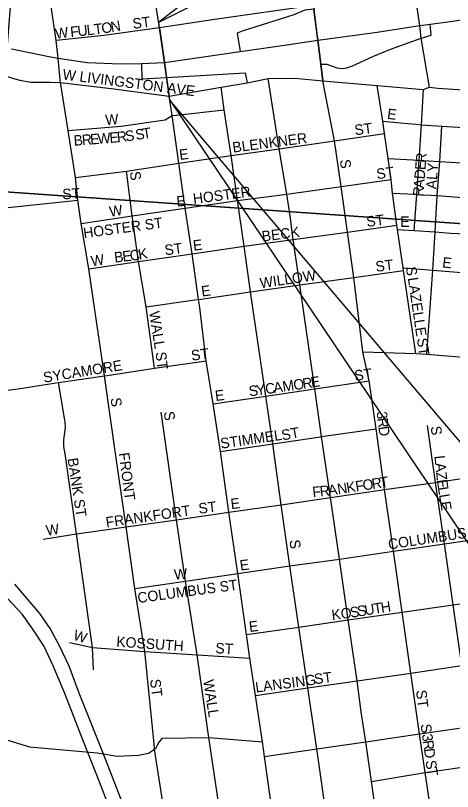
# Model space of a CAD drawing. Extents: x 0 to 34, y -6.2 to 22.
# Drawn here: x 6.622 to 7.019, y 16.756 to 17.461 of the extents above; entities that cross this region are included whole.
import ezdxf

# ---------------------------------------------------------------- set-up
doc = ezdxf.new("R2010")
doc.units = 0
for name, color, linetype in [('GM_X_City_Street', 7, 'Continuous'), ('GM_X_City_Street_Text', 7, 'Continuous'), ('GM_X_Interchange_Ramps', 7, 'Continuous'), ('GM_X_Interstate_Route', 7, 'Continuous'), ('GM_X_Rail_Line', 7, 'Continuous'), ('GM_X_Section', 7, 'Continuous'), ('GM_X_US_Route', 7, 'Continuous'), ('SH_Data', 7, 'Continuous')]:
    doc.layers.add(name, color=color, linetype=linetype)

msp = doc.modelspace()

# ---------------------------------------------------------------- linework, layer by layer
at = {"layer": 'GM_X_City_Street'}
for points in [[(6.66228, 17.40254), (6.66049, 17.4222), (6.65856, 17.43834), (6.64528, 17.52991), (6.63896, 17.57505), (6.63208, 17.62111), (6.62558, 17.66735), (6.61917, 17.71353), (6.60471, 17.80555), (6.59247, 17.89732), (6.57924, 17.99099), (6.57205, 18.04143), (6.57176, 18.04339)], [(6.75255, 17.44995), (6.74524, 17.49671), (6.73878, 17.54435), (6.72556, 17.63506), (6.7249, 17.63939)], [(6.98877, 16.80787), (6.9808, 16.86316), (6.97295, 16.91857), (6.965, 16.97414), (6.95682, 17.03003), (6.94936, 17.08532), (6.94288, 17.12895), (6.93734, 17.15524), (6.92909, 17.22293), (6.92322, 17.2641), (6.91739, 17.30569), (6.91152, 17.34717), (6.90101, 17.40179), (6.89903, 17.41691), (6.89623, 17.43861), (6.89274, 17.46692), (6.89426, 17.47051)], [(6.75255, 17.44995), (6.70191, 17.44305), (6.65856, 17.43834)], [(6.74789, 16.79577), (6.73913, 16.883), (6.73008, 16.94009), (6.72224, 16.99619), (6.71312, 17.05874), (6.70239, 17.13346), (6.68837, 17.23069), (6.68116, 17.27185), (6.6784, 17.29311), (6.67621, 17.31372), (6.66958, 17.35651), (6.66251, 17.40009), (6.66228, 17.40254)], [(6.66251, 17.40009), (6.71103, 17.39445), (6.76126, 17.38765)], [(6.98129, 16.36058), (6.98519, 16.42372), (6.98694, 16.45905), (6.98628, 16.46842), (6.9808, 16.50717), (6.97514, 16.54732), (6.97044, 16.58742), (6.95853, 16.6688), (6.94981, 16.73103), (6.94497, 16.76478), (6.93985, 16.80077), (6.93574, 16.82808), (6.93201, 16.85622), (6.92402, 16.91156), (6.91591, 16.96683), (6.90769, 17.02289), (6.89981, 17.07827), (6.89356, 17.12168), (6.88008, 17.21618), (6.87406, 17.2574), (6.87129, 17.27883), (6.86814, 17.29881), (6.86105, 17.33997), (6.85135, 17.40376)], [(6.98549, 17.15372), (6.97417, 17.22937), (6.97381, 17.23183), (6.96864, 17.26653), (6.96811, 17.27053), (6.96426, 17.29965), (6.96285, 17.31213), (6.96023, 17.33122), (6.9569, 17.3538), (6.9554, 17.36491), (6.95016, 17.39751)], [(6.81124, 17.37548), (6.80857, 17.39581)], [(6.98398, 17.26554), (6.98618, 17.29844), (6.9883, 17.32944), (6.99046, 17.36181), (6.99247, 17.39393)], [(6.66958, 17.35651), (6.71753, 17.36052), (6.75764, 17.36611), (6.76389, 17.37022)], [(6.76389, 17.37022), (6.768, 17.37039), (6.81124, 17.37548)], [(6.9475, 16.29952), (6.94602, 16.36266), (6.94447, 16.42634), (6.94281, 16.46308), (6.93994, 16.48326), (6.9361, 16.51036), (6.9247, 16.59085), (6.91432, 16.66217), (6.89538, 16.79423), (6.88727, 16.84982), (6.87921, 16.90505), (6.87103, 16.96084), (6.86295, 17.01634), (6.85545, 17.07171), (6.84898, 17.11505), (6.8353, 17.20994), (6.82944, 17.25134), (6.82321, 17.29303), (6.81749, 17.33372), (6.81124, 17.37548)], [(6.9554, 17.36491), (6.97135, 17.36342), (6.98538, 17.36224)], [(6.98538, 17.36224), (6.99046, 17.36181), (7.00898, 17.36059), (7.02377, 17.35959), (7.04305, 17.35808), (7.06105, 17.35702), (7.0768, 17.35586), (7.0955, 17.35463)], [(7.00493, 17.30135), (7.00703, 17.32844), (7.00898, 17.36059)], [(6.76997, 17.32682), (6.81749, 17.33372), (6.86105, 17.33997), (6.91152, 17.34717), (6.9569, 17.3538)], [(6.67621, 17.31372), (6.72252, 17.31971), (6.76997, 17.32682)], [(6.96023, 17.33122), (6.9883, 17.32944), (7.00138, 17.32874), (7.00703, 17.32844), (7.02205, 17.32761), (7.04124, 17.32633), (7.05928, 17.32541), (7.07513, 17.32357), (7.09333, 17.32258), (7.17932, 17.31649), (7.21272, 17.31416), (7.2772, 17.31028), (7.32879, 17.30679), (7.37022, 17.30248), (7.37497, 17.30216)], [(6.74807, 17.14058), (6.74031, 17.19619), (6.73351, 17.23735), (6.72774, 17.27907), (6.72252, 17.31971)], [(6.76513, 17.28436), (6.77573, 17.28588), (6.82321, 17.29303), (6.86814, 17.29881), (6.91739, 17.30569), (6.96285, 17.31213)], [(6.96426, 17.29965), (6.98443, 17.29854)], [(6.99551, 17.15319), (7.00082, 17.22971), (7.00284, 17.26431), (7.00463, 17.29736), (7.00493, 17.30135)], [(6.50046, 17.26128), (6.55735, 17.27777), (6.56934, 17.28141), (6.58298, 17.2832), (6.6784, 17.29311)], [(6.98443, 17.29854), (6.98618, 17.29844), (7.00463, 17.29736), (7.02008, 17.29616), (7.03888, 17.29482), (7.05744, 17.29349), (7.07258, 17.29242), (7.09118, 17.29121), (7.09526, 17.29083)], [(6.68116, 17.27185), (6.72774, 17.27907), (6.76513, 17.28436)], [(6.78201, 17.24433), (6.82944, 17.25134), (6.87406, 17.2574), (6.92322, 17.2641), (6.96811, 17.27053)], [(6.96864, 17.26653), (6.98398, 17.26554), (7.00284, 17.26431), (7.01697, 17.26336), (7.03651, 17.26217), (7.05493, 17.26085), (7.07038, 17.25988), (7.08894, 17.25868), (7.108, 17.25664), (7.14201, 17.25363), (7.17553, 17.25134), (7.17773, 17.25111), (7.21989, 17.24793), (7.25478, 17.24516), (7.27152, 17.2441), (7.29026, 17.24266), (7.32481, 17.24037), (7.36585, 17.23773), (7.40163, 17.23554), (7.44233, 17.23315), (7.44451, 17.233)], [(6.68837, 17.23069), (6.73351, 17.23735), (6.78201, 17.24433)], [(6.78795, 17.20304), (6.8353, 17.20994), (6.88008, 17.21618), (6.92909, 17.22293), (6.97417, 17.22937)], [(6.97381, 17.23183), (7.00082, 17.22971), (7.03432, 17.22694), (7.06727, 17.22478)], [(6.74031, 17.19619), (6.7868, 17.20303)], [(6.93734, 17.15524), (6.98549, 17.15372), (6.99551, 17.15319), (7.02829, 17.15034)], [(6.70489, 17.13385), (6.74807, 17.14058), (6.79494, 17.14722)], [(6.64486, 17.12489), (6.66076, 17.12736), (6.70239, 17.13346), (6.70489, 17.13385)], [(6.54599, 17.12007), (6.55145, 17.11592), (6.55621, 17.11505), (6.56156, 17.11407), (6.57194, 17.11497), (6.62409, 17.12166), (6.64486, 17.12489)], [(6.69265, 16.86615), (6.69163, 16.88666), (6.67705, 16.98975), (6.66663, 17.06255), (6.66555, 17.06931), (6.66556, 17.07234), (6.66557, 17.07537), (6.66707, 17.08641), (6.66678, 17.09137), (6.66619, 17.0949), (6.66076, 17.12736)], [(6.80136, 17.10816), (6.84898, 17.11505), (6.89356, 17.12168), (6.94288, 17.12895)], [(6.8291, 16.58565), (6.82024, 16.64708), (6.81213, 16.70338), (6.80479, 16.75388), (6.79742, 16.80456), (6.78661, 16.87995), (6.77622, 16.94687), (6.76796, 17.00266), (6.75398, 17.1005)], [(7.00322, 17.03664), (6.99583, 17.08829)], [(6.89878, 17.07812), (6.89981, 17.07827), (6.94936, 17.08532)], [(6.80781, 17.06482), (6.85545, 17.07171), (6.89878, 17.07812)], [(6.81561, 17.00952), (6.86295, 17.01634), (6.90769, 17.02289), (6.95682, 17.03003), (7.00322, 17.03664), (7.04287, 17.04245)], [(7.04542, 16.74501), (7.04031, 16.77954), (7.03508, 16.81471), (7.02724, 16.87005), (7.01928, 16.92531), (7.01137, 16.98061), (7.00322, 17.03664)], [(6.69646, 16.99251), (6.72224, 16.99619), (6.76796, 17.00266), (6.81561, 17.00952)], [(6.82353, 16.95368), (6.87103, 16.96084), (6.91591, 16.96683), (6.965, 16.97414), (7.01137, 16.98061), (7.05704, 16.98728), (7.10127, 16.99344), (7.13, 16.99743), (7.15851, 17.00116), (7.19129, 16.99884), (7.23458, 16.99599), (7.28124, 16.99293), (7.31163, 16.99092), (7.34133, 16.98882), (7.37633, 16.98634), (7.44129, 16.98221)], [(6.64686, 16.98514), (6.67705, 16.98975), (6.69646, 16.99251)], [(6.73008, 16.94009), (6.77622, 16.94687), (6.82353, 16.95368)], [(6.83156, 16.8982), (6.87921, 16.90505), (6.92402, 16.91156), (6.97295, 16.91857), (7.01928, 16.92531), (7.0653, 16.93194), (7.11013, 16.93831), (7.13803, 16.94224), (7.16549, 16.94618), (7.1679, 16.93411), (7.18697, 16.9335), (7.23038, 16.93054), (7.27701, 16.92747), (7.3069, 16.92549), (7.3368, 16.92357), (7.37158, 16.92099), (7.43727, 16.91687)], [(6.67066, 16.89115), (6.69163, 16.88666), (6.73913, 16.883), (6.78661, 16.87995), (6.83466, 16.87683)], [(6.83974, 16.84289), (6.88727, 16.84982), (6.93201, 16.85622), (6.9808, 16.86316), (7.02724, 16.87005), (7.07341, 16.87657), (7.11767, 16.88261), (7.14621, 16.88683), (7.17434, 16.89007), (7.22701, 16.88596)], [(6.99321, 16.80853), (7.03508, 16.81471), (7.08129, 16.82115), (7.1258, 16.82753), (7.15409, 16.83157), (7.18254, 16.83535), (7.18811, 16.83513), (7.22314, 16.83236), (7.24974, 16.83039), (7.26894, 16.82897), (7.29909, 16.82673), (7.36453, 16.82192), (7.43076, 16.81698), (7.51924, 16.81054), (7.59763, 16.80457), (7.62864, 16.80232), (7.66394, 16.79971), (7.72826, 16.79494), (7.79318, 16.79013), (7.85815, 16.78539)], [(6.52342, 16.82079), (6.5408, 16.82013), (6.54344, 16.81979), (6.58215, 16.81465), (6.60451, 16.80544), (6.63446, 16.7962), (6.69592, 16.79064), (6.71414, 16.78776), (6.73347, 16.78872), (6.74258, 16.79054), (6.74807, 16.79402), (6.74906, 16.79465), (6.75091, 16.79827), (6.75097, 16.79838)], [(6.84792, 16.78744), (6.89538, 16.79423), (6.93985, 16.80077), (6.98877, 16.80787), (6.99321, 16.80853)], [(6.99898, 16.7383), (6.99396, 16.7728), (6.98877, 16.80787)], [(6.75097, 16.79838), (6.75138, 16.79918), (6.75521, 16.80408), (6.79742, 16.80456), (6.84598, 16.80069)], [(6.94497, 16.76478), (6.99396, 16.7728), (7.04031, 16.77954), (7.08659, 16.78643), (7.13133, 16.79281), (7.18775, 16.80024), (7.21441, 16.80115)], [(6.82197, 16.4795), (6.80524, 16.56564), (6.80205, 16.57482), (6.77525, 16.6388), (6.76406, 16.69089), (6.74807, 16.79402), (6.74789, 16.79577)]]:
    msp.add_lwpolyline(points, dxfattribs=at)
at = {"layer": 'GM_X_Interchange_Ramps'}
for points in [[(6.89274, 17.46692), (6.88458, 17.46587), (6.87444, 17.46157), (6.82765, 17.44675), (6.82306, 17.44518), (6.82571, 17.42842)], [(6.89903, 17.41691), (6.90442, 17.41701), (6.91346, 17.41364), (6.91854, 17.41306), (6.92263, 17.41364), (6.92771, 17.4152), (6.94617, 17.42396), (6.96332, 17.43083), (6.99027, 17.44042), (6.99934, 17.44327), (6.99833, 17.45325)], [(6.56706, 17.44086), (6.56677, 17.42931), (6.58863, 17.41913), (6.60038, 17.41215), (6.60649, 17.40815), (6.61815, 17.40433), (6.62513, 17.40239), (6.63577, 17.40064), (6.65275, 17.40038), (6.66251, 17.40009)], [(6.73627, 17.41757), (6.73636, 17.40351), (6.75879, 17.40474), (6.83045, 17.40888), (6.83212, 17.39998)]]:
    msp.add_lwpolyline(points, dxfattribs=at)
at = {"layer": 'GM_X_Interstate_Route'}
for points in [[(6.99833, 17.45325), (7.01691, 17.45571), (7.03717, 17.45857)], [(6.89623, 17.43861), (6.95032, 17.44601), (6.98896, 17.45193), (6.99833, 17.45325)], [(6.73627, 17.41757), (6.75715, 17.41823), (6.82571, 17.42842), (6.86803, 17.43452)], [(6.86803, 17.43452), (6.87815, 17.43598), (6.89623, 17.43861)], [(6.61806, 17.4309), (6.61843, 17.43083), (6.652, 17.42394)], [(6.652, 17.42394), (6.66049, 17.4222)], [(6.66049, 17.4222), (6.68662, 17.41823), (6.71704, 17.41708), (6.73627, 17.41757)]]:
    msp.add_lwpolyline(points, dxfattribs=at)
at = {"layer": 'GM_X_Rail_Line'}
for points in [[(6.78009, 16.34957), (6.78107, 16.44035), (6.78316, 16.54147), (6.78232, 16.55809), (6.78023, 16.57625), (6.77813, 16.58701), (6.77464, 16.59958), (6.76836, 16.61801), (6.74663, 16.67459), (6.72551, 16.72798), (6.70331, 16.78509), (6.69397, 16.80865), (6.67947, 16.84509), (6.67031, 16.86947), (6.66188, 16.88751), (6.65327, 16.90374), (6.64366, 16.91742), (6.62118, 16.94416)], [(6.7671, 16.38071), (6.76836, 16.44803), (6.76892, 16.47122), (6.76961, 16.48602), (6.76975, 16.50684), (6.76989, 16.50963), (6.77017, 16.52695), (6.76919, 16.55237), (6.76766, 16.56592), (6.76473, 16.58226), (6.75869, 16.6048), (6.74536, 16.6426), (6.73956, 16.65773), (6.71953, 16.70877), (6.69497, 16.77185), (6.68219, 16.80403), (6.6666, 16.84455), (6.6559, 16.86984), (6.64738, 16.88797), (6.63745, 16.9033), (6.62776, 16.91688), (6.60983, 16.93579)]]:
    msp.add_lwpolyline(points, dxfattribs=at)
at = {"layer": 'GM_X_Section'}
msp.add_lwpolyline([(6.68124, 18.27598), (6.6863, 18.2758), (7.19351, 18.24276), (7.67976, 18.21035), (7.62278, 17.23025), (6.6036, 17.30139)], close=True, dxfattribs=at)
msp.add_lwpolyline([(6.6036, 17.30139), (7.62278, 17.23025), (7.55762, 16.2055), (6.69487, 16.2608), (6.69615, 16.47781), (6.69681, 16.58979), (6.67582, 16.60734), (6.66866, 16.61383), (6.66566, 16.61915), (6.66266, 16.62447), (6.66079, 16.62789), (6.65777, 16.63056), (6.65098, 16.63439), (6.63588, 16.64282), (6.61965, 16.65201)], dxfattribs=at)
at = {"layer": 'GM_X_US_Route'}
for points in [[(6.98896, 17.45193), (6.98469, 17.48087)], [(6.89426, 17.47051), (6.80056, 17.45702), (6.75255, 17.44995)], [(6.89426, 17.47051), (6.89274, 17.46692), (6.89583, 17.44191)], [(6.75255, 17.44995), (6.75707, 17.41882)], [(6.99784, 17.39587), (6.99027, 17.44042), (6.98896, 17.45193)], [(6.89583, 17.44191), (6.89623, 17.43861), (6.89903, 17.41691), (6.90101, 17.40179)], [(6.75707, 17.41882), (6.75715, 17.41823), (6.75879, 17.40474), (6.76126, 17.38765)], [(6.76126, 17.38765), (6.80857, 17.39581), (6.83212, 17.39998), (6.85135, 17.40376), (6.87552, 17.40425), (6.90101, 17.40179)], [(6.90101, 17.40179), (6.95016, 17.39751), (6.99247, 17.39393), (6.99784, 17.39587)], [(6.99784, 17.39587), (7.0054, 17.39504), (7.01921, 17.39406), (7.02348, 17.39373), (7.02628, 17.39356), (7.04551, 17.39274), (7.0636, 17.39132), (7.07925, 17.39031), (7.09763, 17.38929), (7.16685, 17.38468), (7.18356, 17.38368), (7.28127, 17.37762), (7.37333, 17.37121), (7.40788, 17.36948), (7.48776, 17.36414), (7.52656, 17.36151), (7.62307, 17.35526), (7.63079, 17.35411), (7.67666, 17.33767), (7.70807, 17.3255), (7.77027, 17.3016), (7.8335, 17.2775)], [(6.85879, 16.70975), (6.84792, 16.78744), (6.84598, 16.80069), (6.83974, 16.84289), (6.83466, 16.87683), (6.83156, 16.8982), (6.82353, 16.95368), (6.81561, 17.00952), (6.80781, 17.06482), (6.80136, 17.10816), (6.79494, 17.14722), (6.78911, 17.19556), (6.78795, 17.20304), (6.78201, 17.24433), (6.77573, 17.28588), (6.76997, 17.32682), (6.76389, 17.37022), (6.76126, 17.38765)]]:
    msp.add_lwpolyline(points, dxfattribs=at)
at = {"layer": 'SH_Data'}
for points in [[(10.0459, 19.98884), (6.75174, 17.45513), (10.0459, 19.10806)], [(9.8345, 13.7654), (6.76179, 17.38412), (9.8345, 12.81564)]]:
    msp.add_lwpolyline(points, close=True, dxfattribs=at)
msp.add_lwpolyline([(6.76179, 17.38412), (6.75715, 17.41823), (6.75255, 17.44995), (6.75174, 17.45513)], dxfattribs=at)

# ---------------------------------------------------------------- texts
at = {"layer": 'GM_X_City_Street_Text'}
for s, height, rotation, p in [('T', 0.00947, 6.65944, (6.69346, 17.4438)), ('O', 0.00947, 8.8555, (6.70048, 17.44463)), ('N', 0.00947, 9.77389, (6.70887, 17.44594)), ('ST', 0.00947, 7.11997, (6.72852, 17.44889)), ('W', 0.00947, 8.75753, (6.65847, 17.43971)), ('F', 0.00947, 6.37942, (6.67188, 17.44139)), ('U', 0.00947, 6.37398, (6.6785, 17.44213)), ('L', 0.00947, 6.35226, (6.68678, 17.44306)), ('W LIVINGSTON AVE', 0.0094697, 352.71735, (6.66402, 17.40304)), ('E', 0.00947, 352.87835, (6.95896, 17.36722)), ('W', 0.00947, 4.39613, (6.7036, 17.36139)), ('ST', 0.00947, 7.1351, (6.93019, 17.35222)), ('E', 0.00947, 5.15722, (6.70739, 17.34513)), ('R', 0.00947, 6.49542, (6.71427, 17.34576)), ('S', 0.00947, 7.36074, (6.72187, 17.34663)), ('S', 0.00947, 8.61451, (6.73118, 17.34788)), ('T', 0.00947, 8.86598, (6.73782, 17.34888)), ('B', 0.00947, 4.32608, (6.67483, 17.34265)), ('R', 0.00947, 4.32608, (6.68231, 17.34321)), ('E', 0.00947, 4.32117, (6.68979, 17.34378)), ('W', 0.00947, 4.45001, (6.69646, 17.34429)), ('BLENKNER', 0.00947, 7.45837, (6.81939, 17.33639)), ('E', 0.00947, 7.14855, (6.77102, 17.32972)), ('R', 0.00947, 84.62528, (6.99456, 17.32691)), ('S', 0.00947, 277.12166, (6.91634, 17.32984)), ('E', 0.00947, 85.36651, (6.99402, 17.3203)), ('ALY', 0.00947, 86.05688, (7.00405, 17.30296)), ('ST', 0.00947, 7.60514, (6.95017, 17.31222)), ('D', 0.00947, 85.36159, (6.99335, 17.31199)), ('S', 0.00947, 277.12166, (6.72551, 17.31901)), ('A', 0.00947, 85.37563, (6.99268, 17.30369)), ('ST', 0.00947, 3.57463, (6.66446, 17.29389)), ('HOSTER', 0.00947, 7.39039, (6.78351, 17.28972)), ('R', 0.00947, 85.35733, (6.99207, 17.29621)), ('E', 0.00947, 7.12165, (6.76852, 17.28722)), ('W', 0.00947, 8.76006, (6.70764, 17.27804)), ('HOSTER ST', 0.00947, 7.69714, (6.68392, 17.25856)), ('ST', 0.00947, 7.12165, (6.94102, 17.26889)), ('E', 0.00947, 0.00001, (6.97124, 17.2689)), ('BECK', 0.00947, 7.27471, (6.84604, 17.25556)), ('E', 0.00947, 7.12165, (6.78352, 17.24722)), ('K', 0.00947, 9.73855, (6.73394, 17.23905)), ('ST', 0.00947, 7.13342, (6.75768, 17.24305)), ('W', 0.00947, 8.74111, (6.69097, 17.23305)), ('B', 0.00947, 6.61905, (6.71187, 17.23639)), ('E', 0.00947, 6.63443, (6.71932, 17.23725)), ('C', 0.00947, 7.25854, (6.72606, 17.23803)), ('ST', 0.00947, 7.11997, (6.94935, 17.22805)), ('E', 0.00947, 352.68521, (7.00897, 17.23222)), ('WILLOW', 0.00947, 8.36746, (6.84434, 17.21305)), ('S', 0.00947, 277.12166, (6.97634, 17.23234)), ('LAZELLE', 0.00947, 278.39178, (6.978, 17.22238)), ('E', 0.00947, 7.12165, (6.79102, 17.20555)), ('WALL', 0.00947, 278.74659, (6.743, 17.19156)), ('ST', 0.00947, 277.60324, (6.98634, 17.16735)), ('ST', 0.00947, 7.58892, (6.78184, 17.14722)), ('ST', 0.00947, 277.13512, (6.74884, 17.15484)), ('SYCAMORE', 0.00947, 9.14091, (6.64765, 17.12721)), ('ST', 0.00947, 7.59083, (6.93017, 17.12888)), ('M', 0.00947, 8.02192, (6.86486, 17.11902)), ('O', 0.00947, 8.02502, (6.87476, 17.12042)), ('R', 0.00947, 8.07139, (6.88302, 17.12159)), ('E', 0.00947, 9.46887, (6.8907, 17.12268)), ('S', 0.00947, 8.02966, (6.83432, 17.11472)), ('Y', 0.00947, 8.02502, (6.84092, 17.11565)), ('C', 0.00947, 8.02423, (6.84918, 17.11681)), ('A', 0.00947, 8.02502, (6.8566, 17.11786)), ('E', 0.00947, 7.12165, (6.80352, 17.11055)), ('S', 0.00947, 277.12166, (6.70801, 17.11317)), ('S', 0.00947, 277.12166, (6.75634, 17.10067)), ('3', 0.00947, 276.41259, (6.94968, 17.10065)), ('R', 0.00947, 276.66592, (6.95033, 17.0948)), ('ST', 0.00947, 10.6279, (6.86424, 17.0747)), ('D', 0.00947, 278.6115, (6.95125, 17.08701)), ('S', 0.00947, 277.12166, (6.99884, 17.08734)), ('STIMMEL', 0.00947, 8.25838, (6.80848, 17.06721)), ('FRONT', 0.00947, 277.42716, (6.71551, 17.06318)), ('L', 0.00947, 275.93895, (7.00218, 17.06063)), ('BANK ST', 0.00947, 278.67183, (6.66884, 17.05822)), ('A', 0.00947, 275.93464, (7.00287, 17.054)), ('Z', 0.00947, 276.07107, (7.00373, 17.04569)), ('K', 0.00947, 8.58164, (6.92292, 17.02702)), ('F', 0.00947, 8.55508, (6.93116, 17.02826)), ('O', 0.00947, 8.58164, (6.93775, 17.02925)), ('R', 0.00947, 8.55598, (6.94599, 17.03049)), ('T', 0.00947, 8.58954, (6.95341, 17.03161)), ('E', 0.00947, 277.67384, (7.00447, 17.03878)), ('F', 0.00947, 6.07766, (6.89189, 17.02306)), ('R', 0.00947, 6.25682, (6.89855, 17.02377)), ('A', 0.00947, 7.88388, (6.90629, 17.02462)), ('N', 0.00947, 8.5464, (6.91467, 17.02578)), ('L', 0.00947, 278.82762, (7.00539, 17.03196)), ('L', 0.00947, 278.86599, (7.00642, 17.02536)), ('ST', 0.00947, 7.12165, (6.78852, 17.00805)), ('E', 0.00947, 7.12165, (6.81769, 17.01222)), ('E', 0.00947, 278.86599, (7.00745, 17.01878)), ('FRANKFORT', 0.00947, 8.22666, (6.70432, 16.99555)), ('W', 0.00947, 8.75753, (6.65014, 16.98804)), ('COLUMBUS', 0.00947, 8.596, (6.96097, 16.97555)), ('S', 0.00947, 277.14856, (6.87051, 16.98401)), ('E', 0.00947, 7.12165, (6.82602, 16.95639)), ('W', 0.00947, 4.78022, (6.76609, 16.94806)), ('COLUMBUS ST', 0.0094697, 7.63178, (6.73312, 16.9269)), ('S', 0.00947, 9.14246, (6.93291, 16.91457)), ('U', 0.00947, 9.14248, (6.93949, 16.91562)), ('T', 0.00947, 9.14246, (6.94772, 16.91695)), ('H', 0.00947, 9.14248, (6.9543, 16.91801)), ('K', 0.00947, 6.74815, (6.90936, 16.91139)), ('O', 0.00947, 7.55262, (6.91778, 16.91239)), ('S', 0.00947, 8.96582, (6.92629, 16.91352)), ('E', 0.00947, 7.11829, (6.83435, 16.90055)), ('W', 0.00947, 342.902, (6.67343, 16.89382)), ('KOSSUTH', 0.00947, 356.13378, (6.71302, 16.88723)), ('ST', 0.00947, 356.42537, (6.80302, 16.8814)), ('LANSING', 0.00947, 7.59393, (6.84017, 16.84555)), ('ST', 0.00947, 7.12165, (6.89352, 16.85305)), ('ST', 0.00947, 277.12166, (6.74384, 16.85734)), ('WALL', 0.00947, 278.53131, (6.79217, 16.85655)), ('ST', 0.00947, 277.13512, (6.98551, 16.84734)), ('S', 0.00947, 277.72826, (6.98967, 16.81652)), ('3', 0.00947, 277.73705, (6.9909, 16.80744)), ('R', 0.00947, 277.72143, (6.99169, 16.80166)), ('D', 0.00947, 277.71596, (6.9927, 16.79422)), ('S', 0.00947, 277.72826, (6.99415, 16.78348)), ('T', 0.00947, 279.24229, (6.99509, 16.7766))]:
    msp.add_text(s, height=height, rotation=rotation, dxfattribs=at).set_placement(p)

doc.saveas('drawing.dxf')
